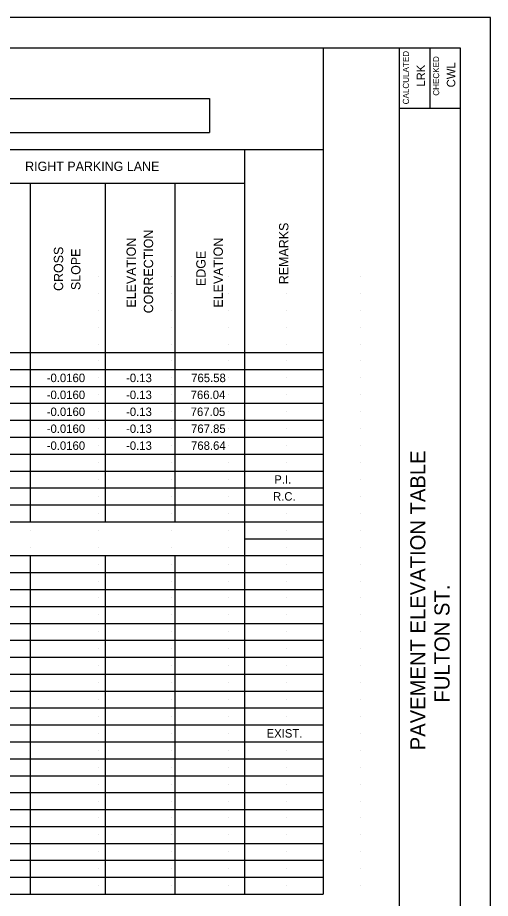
# Model space of a CAD drawing. Extents: x -15.4 to 18.6, y -12.6 to 9.4.
# Drawn here: x 10.82 to 18.64, y -5.18 to 9.39 of the extents above; entities that cross this region are included whole.
import ezdxf

# ---------------------------------------------------------------- set-up
doc = ezdxf.new("R2010")
doc.units = 0
for name, color, linetype in [('SH_Border', 7, 'Continuous'), ('SH_Cut_Line', 7, 'Continuous'), ('SH_Data', 7, 'Continuous'), ('SH_Text', 7, 'Continuous')]:
    doc.layers.add(name, color=color, linetype=linetype)

msp = doc.modelspace()

# ---------------------------------------------------------------- linework, layer by layer
at = {"layer": 'SH_Border'}
for p, q in [((17.143, -12.112), (17.143, 8.888)), ((17.643, 8.888), (17.643, 7.888)), ((17.143, 7.888), (18.143, 7.888))]:
    msp.add_line(p, q, dxfattribs=at)
msp.add_lwpolyline([(-13.357, 8.888), (18.143, 8.888), (18.143, -12.112), (-13.357, -12.112)], close=True, dxfattribs=at)
at = {"layer": 'SH_Cut_Line'}
msp.add_lwpolyline([(-15.357, -12.612), (18.643, -12.612), (18.643, 9.388), (-15.357, 9.388)], close=True, dxfattribs=at)
at = {"layer": 'SH_Data'}
for p, q in [((-12.667, 8.888), (15.877, 8.888)), ((15.877, 8.888), (15.877, -5.112)), ((-11.514, 8.048), (13.999, 8.048)), ((13.999, 8.048), (13.999, 7.488)), ((-11.514, 7.488), (13.999, 7.488)), ((-12.667, 7.208), (15.877, 7.208)), ((14.576, 7.208), (14.576, -5.112)), ((-12.667, 6.648), (14.576, 6.648)), ((11.034, 6.648), (11.034, 1.048)), ((12.27, 6.648), (12.27, 1.048)), ((13.423, 6.648), (13.423, 1.048)), ((11.043, 5.108), (11.043, 5.108)), ((12.168, 5.108), (12.168, 5.108)), ((13.368, 5.108), (13.368, 5.108)), ((14.318, 5.108), (14.318, 5.108)), ((15.268, 5.108), (15.268, 5.108)), ((16.493, 5.108), (16.493, 5.108)), ((11.043, 4.828), (11.043, 4.828)), ((12.168, 4.828), (12.168, 4.828)), ((13.368, 4.828), (13.368, 4.828)), ((14.318, 4.828), (14.318, 4.828)), ((15.268, 4.828), (15.268, 4.828)), ((16.493, 4.828), (16.493, 4.828)), ((11.043, 4.548), (11.043, 4.548)), ((12.168, 4.548), (12.168, 4.548)), ((13.368, 4.548), (13.368, 4.548)), ((14.318, 4.548), (14.318, 4.548)), ((15.268, 4.548), (15.268, 4.548)), ((16.493, 4.548), (16.493, 4.548)), ((11.043, 4.268), (11.043, 4.268)), ((12.168, 4.268), (12.168, 4.268)), ((13.368, 4.268), (13.368, 4.268)), ((14.318, 4.268), (14.318, 4.268)), ((15.268, 4.268), (15.268, 4.268)), ((16.493, 4.268), (16.493, 4.268)), ((11.043, 3.988), (11.043, 3.988)), ((12.168, 3.988), (12.168, 3.988)), ((13.368, 3.988), (13.368, 3.988)), ((14.318, 3.988), (14.318, 3.988)), ((15.268, 3.988), (15.268, 3.988)), ((16.493, 3.988), (16.493, 3.988)), ((-12.667, 3.848), (15.877, 3.848)), ((11.043, 3.708), (11.043, 3.708)), ((12.168, 3.708), (12.168, 3.708)), ((13.368, 3.708), (13.368, 3.708)), ((14.318, 3.708), (14.318, 3.708)), ((15.268, 3.708), (15.268, 3.708)), ((16.493, 3.708), (16.493, 3.708)), ((-12.667, 3.568), (15.877, 3.568)), ((11.043, 3.428), (11.043, 3.428)), ((12.168, 3.428), (12.168, 3.428)), ((13.368, 3.428), (13.368, 3.428)), ((14.318, 3.428), (14.318, 3.428)), ((15.268, 3.428), (15.268, 3.428)), ((16.493, 3.428), (16.493, 3.428)), ((-12.667, 3.288), (15.877, 3.288)), ((11.043, 3.148), (11.043, 3.148)), ((12.168, 3.148), (12.168, 3.148)), ((13.368, 3.148), (13.368, 3.148)), ((14.318, 3.148), (14.318, 3.148)), ((15.268, 3.148), (15.268, 3.148)), ((16.493, 3.148), (16.493, 3.148)), ((-12.667, 3.008), (15.877, 3.008)), ((11.043, 2.868), (11.043, 2.868)), ((12.168, 2.868), (12.168, 2.868)), ((13.368, 2.868), (13.368, 2.868)), ((14.318, 2.868), (14.318, 2.868)), ((15.268, 2.868), (15.268, 2.868)), ((16.493, 2.868), (16.493, 2.868)), ((-12.667, 2.728), (15.877, 2.728)), ((11.043, 2.588), (11.043, 2.588)), ((12.168, 2.588), (12.168, 2.588)), ((13.368, 2.588), (13.368, 2.588)), ((14.318, 2.588), (14.318, 2.588)), ((15.268, 2.588), (15.268, 2.588)), ((16.493, 2.588), (16.493, 2.588)), ((-12.667, 2.448), (15.877, 2.448)), ((11.043, 2.308), (11.043, 2.308)), ((12.168, 2.308), (12.168, 2.308)), ((13.368, 2.308), (13.368, 2.308)), ((14.318, 2.308), (14.318, 2.308)), ((15.268, 2.308), (15.268, 2.308)), ((16.493, 2.308), (16.493, 2.308)), ((-12.667, 2.168), (15.877, 2.168)), ((11.043, 2.028), (11.043, 2.028)), ((12.168, 2.028), (12.168, 2.028)), ((13.368, 2.028), (13.368, 2.028)), ((14.318, 2.028), (14.318, 2.028)), ((15.268, 2.028), (15.268, 2.028)), ((16.493, 2.028), (16.493, 2.028)), ((-12.667, 1.888), (15.877, 1.888)), ((-12.667, 1.608), (15.877, 1.608)), ((11.043, 1.748), (11.043, 1.748)), ((12.168, 1.748), (12.168, 1.748)), ((13.368, 1.748), (13.368, 1.748)), ((14.318, 1.748), (14.318, 1.748)), ((15.268, 1.748), (15.268, 1.748)), ((16.493, 1.748), (16.493, 1.748)), ((11.043, 1.468), (11.043, 1.468)), ((12.168, 1.468), (12.168, 1.468)), ((13.368, 1.468), (13.368, 1.468)), ((14.318, 1.468), (14.318, 1.468)), ((15.268, 1.468), (15.268, 1.468)), ((16.493, 1.468), (16.493, 1.468)), ((-12.667, 1.328), (15.877, 1.328)), ((11.043, 1.188), (11.043, 1.188)), ((12.168, 1.188), (12.168, 1.188)), ((13.368, 1.188), (13.368, 1.188)), ((14.318, 1.188), (14.318, 1.188)), ((15.268, 1.188), (15.268, 1.188)), ((16.493, 1.188), (16.493, 1.188)), ((-12.667, 1.048), (15.877, 1.048)), ((11.043, 0.908), (11.043, 0.908)), ((12.168, 0.908), (12.168, 0.908)), ((13.368, 0.908), (13.368, 0.908)), ((14.318, 0.908), (14.318, 0.908)), ((15.268, 0.908), (15.268, 0.908)), ((16.493, 0.908), (16.493, 0.908)), ((14.576, 0.768), (15.877, 0.768)), ((11.043, 0.628), (11.043, 0.628)), ((12.168, 0.628), (12.168, 0.628)), ((13.368, 0.628), (13.368, 0.628)), ((14.318, 0.628), (14.318, 0.628)), ((15.268, 0.628), (15.268, 0.628)), ((16.493, 0.628), (16.493, 0.628)), ((-12.667, 0.488), (15.877, 0.488)), ((11.034, 0.488), (11.034, -5.112)), ((12.27, 0.488), (12.27, -5.112)), ((13.423, 0.488), (13.423, -5.112)), ((11.043, 0.348), (11.043, 0.348)), ((12.168, 0.348), (12.168, 0.348)), ((13.368, 0.348), (13.368, 0.348)), ((14.318, 0.348), (14.318, 0.348)), ((15.268, 0.348), (15.268, 0.348)), ((16.493, 0.348), (16.493, 0.348)), ((-12.667, 0.208), (15.877, 0.208)), ((11.043, 0.068), (11.043, 0.068)), ((12.168, 0.068), (12.168, 0.068)), ((13.368, 0.068), (13.368, 0.068)), ((14.318, 0.068), (14.318, 0.068)), ((15.268, 0.068), (15.268, 0.068)), ((16.493, 0.068), (16.493, 0.068)), ((-12.667, -0.072), (15.877, -0.072)), ((11.043, -0.212), (11.043, -0.212)), ((12.168, -0.212), (12.168, -0.212)), ((13.368, -0.212), (13.368, -0.212)), ((14.318, -0.212), (14.318, -0.212)), ((15.268, -0.212), (15.268, -0.212)), ((16.493, -0.212), (16.493, -0.212)), ((-12.667, -0.352), (15.877, -0.352)), ((11.043, -0.492), (11.043, -0.492)), ((12.168, -0.492), (12.168, -0.492)), ((13.368, -0.492), (13.368, -0.492)), ((14.318, -0.492), (14.318, -0.492)), ((15.268, -0.492), (15.268, -0.492)), ((16.493, -0.492), (16.493, -0.492)), ((-12.667, -0.632), (15.877, -0.632)), ((11.043, -0.772), (11.043, -0.772)), ((12.168, -0.772), (12.168, -0.772)), ((13.368, -0.772), (13.368, -0.772)), ((14.318, -0.772), (14.318, -0.772)), ((15.268, -0.772), (15.268, -0.772)), ((16.493, -0.772), (16.493, -0.772)), ((-12.667, -0.912), (15.877, -0.912)), ((11.043, -1.052), (11.043, -1.052)), ((12.168, -1.052), (12.168, -1.052)), ((13.368, -1.052), (13.368, -1.052)), ((14.318, -1.052), (14.318, -1.052)), ((15.268, -1.052), (15.268, -1.052)), ((16.493, -1.052), (16.493, -1.052)), ((-12.667, -1.192), (15.877, -1.192)), ((11.043, -1.332), (11.043, -1.332)), ((12.168, -1.332), (12.168, -1.332)), ((13.368, -1.332), (13.368, -1.332)), ((14.318, -1.332), (14.318, -1.332)), ((15.268, -1.332), (15.268, -1.332)), ((16.493, -1.332), (16.493, -1.332)), ((-12.667, -1.472), (15.877, -1.472)), ((11.043, -1.612), (11.043, -1.612)), ((12.168, -1.612), (12.168, -1.612)), ((13.368, -1.612), (13.368, -1.612)), ((14.318, -1.612), (14.318, -1.612)), ((15.268, -1.612), (15.268, -1.612)), ((16.493, -1.612), (16.493, -1.612)), ((-12.667, -1.752), (15.877, -1.752)), ((11.043, -1.892), (11.043, -1.892)), ((12.168, -1.892), (12.168, -1.892)), ((13.368, -1.892), (13.368, -1.892)), ((14.318, -1.892), (14.318, -1.892)), ((15.268, -1.892), (15.268, -1.892)), ((16.493, -1.892), (16.493, -1.892)), ((-12.667, -2.032), (15.877, -2.032)), ((11.043, -2.172), (11.043, -2.172)), ((12.168, -2.172), (12.168, -2.172)), ((13.368, -2.172), (13.368, -2.172)), ((14.318, -2.172), (14.318, -2.172)), ((15.268, -2.172), (15.268, -2.172)), ((16.493, -2.172), (16.493, -2.172)), ((-12.667, -2.312), (15.877, -2.312)), ((11.043, -2.452), (11.043, -2.452)), ((12.168, -2.452), (12.168, -2.452)), ((13.368, -2.452), (13.368, -2.452)), ((14.318, -2.452), (14.318, -2.452)), ((15.268, -2.452), (15.268, -2.452)), ((16.493, -2.452), (16.493, -2.452)), ((-12.667, -2.592), (15.877, -2.592)), ((11.043, -2.732), (11.043, -2.732)), ((12.168, -2.732), (12.168, -2.732)), ((13.368, -2.732), (13.368, -2.732)), ((14.318, -2.732), (14.318, -2.732)), ((15.268, -2.732), (15.268, -2.732)), ((16.493, -2.732), (16.493, -2.732)), ((-12.667, -2.872), (15.877, -2.872)), ((11.043, -3.012), (11.043, -3.012)), ((12.168, -3.012), (12.168, -3.012)), ((13.368, -3.012), (13.368, -3.012)), ((14.318, -3.012), (14.318, -3.012)), ((15.268, -3.012), (15.268, -3.012)), ((16.493, -3.012), (16.493, -3.012)), ((-12.667, -3.152), (15.877, -3.152)), ((11.043, -3.292), (11.043, -3.292)), ((12.168, -3.292), (12.168, -3.292)), ((13.368, -3.292), (13.368, -3.292)), ((14.318, -3.292), (14.318, -3.292)), ((15.268, -3.292), (15.268, -3.292)), ((16.493, -3.292), (16.493, -3.292)), ((-12.667, -3.432), (15.877, -3.432)), ((11.043, -3.572), (11.043, -3.572)), ((12.168, -3.572), (12.168, -3.572)), ((13.368, -3.572), (13.368, -3.572)), ((14.318, -3.572), (14.318, -3.572)), ((15.268, -3.572), (15.268, -3.572)), ((16.493, -3.572), (16.493, -3.572)), ((-12.667, -3.712), (15.877, -3.712)), ((11.043, -3.852), (11.043, -3.852)), ((12.168, -3.852), (12.168, -3.852)), ((13.368, -3.852), (13.368, -3.852)), ((14.318, -3.852), (14.318, -3.852)), ((15.268, -3.852), (15.268, -3.852)), ((16.493, -3.852), (16.493, -3.852)), ((-8.121, -3.992), (15.877, -3.992)), ((11.043, -4.132), (11.043, -4.132)), ((12.168, -4.132), (12.168, -4.132)), ((13.368, -4.132), (13.368, -4.132)), ((14.318, -4.132), (14.318, -4.132)), ((15.268, -4.132), (15.268, -4.132)), ((16.493, -4.132), (16.493, -4.132)), ((-8.121, -4.272), (15.877, -4.272)), ((11.043, -4.412), (11.043, -4.412)), ((12.168, -4.412), (12.168, -4.412)), ((13.368, -4.412), (13.368, -4.412)), ((14.318, -4.412), (14.318, -4.412)), ((15.268, -4.412), (15.268, -4.412)), ((16.493, -4.412), (16.493, -4.412)), ((-12.667, -4.552), (15.877, -4.552)), ((11.043, -4.692), (11.043, -4.692)), ((12.168, -4.692), (12.168, -4.692)), ((13.368, -4.692), (13.368, -4.692)), ((14.318, -4.692), (14.318, -4.692)), ((15.268, -4.692), (15.268, -4.692)), ((16.493, -4.692), (16.493, -4.692)), ((-12.667, -4.832), (15.877, -4.832)), ((11.043, -4.972), (11.043, -4.972)), ((12.168, -4.972), (12.168, -4.972)), ((13.368, -4.972), (13.368, -4.972)), ((14.318, -4.972), (14.318, -4.972)), ((15.268, -4.972), (15.268, -4.972)), ((16.493, -4.972), (16.493, -4.972)), ((-12.667, -5.112), (15.877, -5.112))]:
    msp.add_line(p, q, dxfattribs=at)

# ---------------------------------------------------------------- texts
for s, height, p in [('CALCULATED', 0.1, (17.296, 7.953)), ('CHECKED', 0.1, (17.796, 8.096)), ('LRK', 0.14, (17.563, 8.245)), ('CWL', 0.14, (18.063, 8.234)), ('PAVEMENT ELEVATION TABLE', 0.25, (17.568, -2.732)), ('             FULTON ST.             ', 0.25, (17.968, -3.149))]:
    msp.add_text(s, height=height, rotation=90, dxfattribs=at).set_placement(p)
at = {"layer": 'SH_Text'}
for s, height, p in [('RIGHT PARKING LANE', 0.154, (10.949, 6.851)), ('-0.0160', 0.14, (11.306, 3.358)), ('-0.13', 0.14, (12.618, 3.358)), ('765.58', 0.14, (13.695, 3.358)), ('-0.0160', 0.14, (11.306, 3.078)), ('-0.13', 0.14, (12.618, 3.078)), ('766.04', 0.14, (13.687, 3.078)), ('-0.0160', 0.14, (11.306, 2.798)), ('-0.13', 0.14, (12.618, 2.798)), ('767.05', 0.14, (13.687, 2.798)), ('-0.0160', 0.14, (11.306, 2.518)), ('-0.13', 0.14, (12.618, 2.518)), ('767.85', 0.14, (13.693, 2.518)), ('-0.0160', 0.14, (11.306, 2.238)), ('-0.13', 0.14, (12.618, 2.238)), ('768.64', 0.14, (13.693, 2.238)), ('P.I.', 0.14, (15.069, 1.678)), ('R.C.', 0.14, (15.048, 1.398)), ('EXIST.', 0.14, (14.942, -2.522))]:
    msp.add_text(s, height=height, dxfattribs=at).set_placement(p)
for s, p in [('REMARKS', (15.303, 4.978)), ('CORRECTION', (13.066, 4.497)), ('ELEVATION', (12.78, 4.591)), ('ELEVATION', (14.219, 4.591)), ('CROSS', (11.578, 4.866)), ('SLOPE', (11.864, 4.881)), ('EDGE', (13.933, 4.948))]:
    msp.add_text(s, height=0.154, rotation=90, dxfattribs=at).set_placement(p)

doc.saveas('drawing.dxf')
